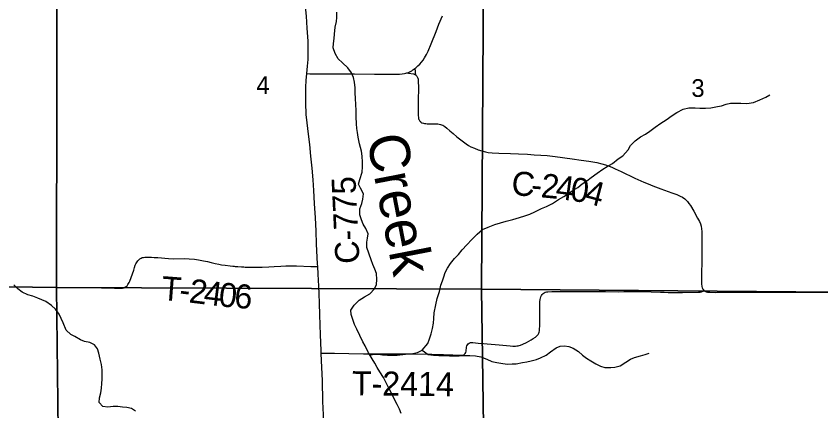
# Model space of a CAD drawing. Extents: x 1874609 to 2204689, y 815661 to 1281160.
# Drawn here: x 2023837 to 2033877, y 986389 to 991319 of the extents above; entities that cross this region are included whole.
import ezdxf

# ---------------------------------------------------------------- set-up
doc = ezdxf.new("R2010")
doc.units = 0
for name, color, linetype in [('GM_X_County_Road', 7, 'Continuous'), ('GM_X_County_Road_Text', 7, 'Continuous'), ('GM_X_Minor_River', 7, 'Continuous'), ('GM_X_Minor_River_Text', 7, 'Continuous'), ('GM_X_Section', 7, 'Continuous'), ('GM_X_Section_Text', 7, 'Continuous'), ('GM_X_Township_Road', 7, 'Continuous'), ('GM_X_Township_Road_Text', 7, 'Continuous')]:
    doc.layers.add(name, color=color, linetype=linetype)

msp = doc.modelspace()

# ---------------------------------------------------------------- linework, layer by layer
at = {"layer": 'GM_X_County_Road'}
for points in [[(2027465, 990602), (2027473, 990694), (2027480, 990776), (2027481, 990841), (2027482, 990940), (2027479, 991006), (2027469, 991169), (2027458, 991317), (2027449, 991398), (2027439, 991463), (2027425, 991528), (2027407, 991608), (2027369, 991750), (2027342, 991845), (2027290, 992035), (2027252, 992177), (2027215, 992320), (2027154, 992575), (2027096, 992831), (2027074, 992944), (2027062, 993008), (2027054, 993073), (2027048, 993138), (2027047, 993160)], [(2028812, 990664), (2028825, 990674), (2028850, 990696), (2028873, 990719), (2028894, 990743), (2028914, 990769), (2028932, 990796), (2028956, 990838), (2028977, 990882), (2029014, 990973), (2029075, 991126), (2029112, 991217), (2029157, 991323)], [(2028712, 990610), (2028719, 990612), (2028731, 990616), (2028744, 990622), (2028757, 990629), (2028772, 990637), (2028787, 990647), (2028799, 990655), (2028807, 990660), (2028812, 990664)], [(2028812, 990664), (2028812, 990656), (2028814, 990635), (2028815, 990621), (2028816, 990610), (2028818, 990591), (2028818, 990587)], [(2027600, 988191), (2027598, 988226), (2027586, 988472), (2027579, 988636), (2027571, 988800), (2027561, 988980), (2027551, 989143), (2027548, 989208), (2027543, 989274), (2027529, 989421), (2027514, 989568), (2027499, 989714), (2027488, 989812), (2027457, 990089), (2027454, 990139), (2027450, 990187), (2027449, 990269), (2027449, 990318), (2027452, 990432), (2027456, 990514), (2027465, 990602)], [(2027465, 990602), (2027503, 990600), (2027568, 990598), (2027634, 990597), (2027749, 990596), (2028060, 990596), (2028307, 990595), (2028536, 990593), (2028618, 990595), (2028651, 990598), (2028683, 990602), (2028699, 990606), (2028712, 990610)], [(2028712, 990610), (2028733, 990607), (2028794, 990596), (2028801, 990594), (2028807, 990592), (2028812, 990590), (2028815, 990588), (2028818, 990587)], [(2028818, 990587), (2028821, 990585), (2028823, 990583), (2028827, 990580), (2028832, 990574), (2028837, 990567), (2028840, 990561), (2028844, 990553), (2028848, 990543), (2028851, 990531), (2028853, 990516), (2028854, 990499), (2028855, 990434), (2028853, 990254), (2028854, 990072), (2028855, 990056), (2028858, 990039), (2028861, 990029), (2028864, 990023), (2028869, 990014), (2028873, 990008), (2028880, 990001), (2028886, 989996), (2028900, 989988), (2028917, 989982), (2028933, 989978), (2028950, 989976), (2028964, 989975), (2028983, 989975), (2029082, 989973), (2029099, 989972), (2029113, 989970), (2029129, 989967), (2029144, 989962), (2029159, 989955), (2029173, 989948), (2029186, 989939), (2029212, 989919), (2029249, 989887), (2029287, 989855), (2029336, 989813), (2029400, 989761), (2029453, 989722), (2029481, 989704), (2029510, 989688), (2029555, 989668), (2029600, 989650), (2029647, 989635), (2029694, 989622), (2029727, 989616), (2029776, 989611), (2029858, 989608), (2030005, 989604), (2030104, 989601), (2030218, 989593), (2030300, 989587), (2030382, 989583), (2030463, 989577), (2030561, 989566), (2030772, 989537), (2030886, 989522), (2030983, 989508), (2031080, 989490), (2031143, 989476), (2031190, 989463), (2031237, 989446), (2031267, 989434), (2031311, 989413), (2031385, 989379), (2031554, 989297), (2031669, 989247), (2031721, 989226), (2031780, 989201), (2031879, 989161), (2032016, 989114), (2032078, 989092), (2032122, 989072), (2032150, 989056), (2032177, 989038), (2032200, 989016), (2032211, 989004), (2032231, 988979), (2032249, 988952), (2032290, 988882), (2032339, 988797), (2032361, 988754), (2032374, 988725), (2032383, 988694), (2032389, 988663), (2032392, 988631), (2032393, 988582), (2032393, 988500), (2032392, 988368), (2032391, 988237), (2032389, 988122), (2032388, 988040), (2032389, 987975), (2032393, 987942), (2032396, 987925), (2032403, 987909), (2032419, 987889)], [(2027644, 987111), (2027643, 987145), (2027635, 987341), (2027625, 987587), (2027621, 987735), (2027617, 987850), (2027613, 987948), (2027606, 988095), (2027600, 988191)], [(2032419, 987889), (2032444, 987875), (2032460, 987873), (2032492, 987870), (2032558, 987869), (2032672, 987870), (2032738, 987871), (2032804, 987871), (2032885, 987871), (2032999, 987871), (2033081, 987870), (2033179, 987870), (2033393, 987870), (2033458, 987870), (2033556, 987871), (2033687, 987871), (2033785, 987871), (2033999, 987869)], [(2027701, 985206), (2027703, 985275), (2027700, 985423), (2027691, 985685), (2027674, 986259), (2027665, 986505), (2027657, 986768), (2027646, 987013), (2027644, 987111)]]:
    msp.add_lwpolyline(points, dxfattribs=at)
at = {"layer": 'GM_X_Minor_River'}
for points in [[(2028331, 987968), (2028337, 988030), (2028331, 988104), (2028311, 988158), (2028287, 988219), (2028265, 988277), (2028213, 988429), (2028213, 988495), (2028219, 988547), (2028227, 988600), (2028201, 988668), (2028167, 988722), (2028145, 988776), (2028126, 988836), (2028124, 988912), (2028148, 988981), (2028162, 989035), (2028170, 989101), (2028132, 989169), (2028108, 989219), (2028126, 989277), (2028152, 989372), (2028156, 989436), (2028156, 989496), (2028152, 989568), (2028144, 989632), (2028121, 989724), (2028103, 989807), (2028095, 989867), (2028089, 989917), (2028085, 989975), (2028079, 990063), (2028081, 990132), (2028075, 990222), (2028069, 990282), (2028067, 990368), (2028065, 990422), (2028057, 990492), (2028047, 990551), (2028021, 990611), (2027973, 990671), (2027909, 990735), (2027855, 990785), (2027817, 990850), (2027793, 990922), (2027797, 990978), (2027805, 991038), (2027809, 991092), (2027818, 991180), (2027832, 991251), (2027836, 991303), (2027836, 991367)], [(2028251, 987086), (2028300, 987098), (2028354, 987096), (2028408, 987088), (2028470, 987084), (2028522, 987084), (2028589, 987086), (2028663, 987092), (2028729, 987100), (2028787, 987106), (2028845, 987118), (2028903, 987148), (2028971, 987230), (2028994, 987288), (2029014, 987350), (2029030, 987420), (2029042, 987486), (2029046, 987543), (2029054, 987613), (2029072, 987713), (2029088, 987793), (2029119, 987879), (2029137, 987958), (2029155, 988012), (2029171, 988062), (2029191, 988116), (2029217, 988170), (2029257, 988228), (2029305, 988292), (2029354, 988342), (2029402, 988401), (2029458, 988463), (2029522, 988531), (2029588, 988597), (2029657, 988653), (2029727, 988683), (2029809, 988717), (2029881, 988737), (2029949, 988757), (2030034, 988779), (2030116, 988805), (2030184, 988825), (2030246, 988847), (2030306, 988873), (2030390, 988917), (2030455, 988943), (2030529, 988981), (2030605, 989030), (2030669, 989066), (2030727, 989104), (2030788, 989146), (2030844, 989178), (2030900, 989224), (2030958, 989264), (2031010, 989302), (2031086, 989358), (2031155, 989406), (2031209, 989442), (2031275, 989480), (2031349, 989537), (2031405, 989575), (2031472, 989649), (2031502, 989705), (2031558, 989761), (2031626, 989813), (2031690, 989845), (2031742, 989883), (2031809, 989931), (2031879, 989981), (2031947, 990025), (2032019, 990076), (2032081, 990116), (2032158, 990156), (2032230, 990174), (2032306, 990174), (2032366, 990168), (2032438, 990168), (2032502, 990174), (2032585, 990188), (2032637, 990200), (2032695, 990220), (2032749, 990232), (2032823, 990232), (2032877, 990230), (2032953, 990228), (2033036, 990240), (2033114, 990274), (2033190, 990306), (2033240, 990334)], [(2025327, 986387), (2025277, 986419), (2025219, 986431), (2025162, 986438), (2025104, 986446), (2025046, 986444), (2024980, 986436), (2024920, 986444), (2024872, 986496), (2024878, 986552), (2024892, 986614), (2024904, 986672), (2024908, 986730), (2024910, 986787), (2024910, 986901), (2024901, 986967), (2024887, 987037), (2024869, 987109), (2024851, 987164), (2024813, 987214), (2024757, 987242), (2024692, 987258), (2024642, 987278), (2024570, 987318), (2024520, 987344), (2024460, 987398), (2024422, 987491), (2024398, 987543), (2024374, 987597), (2024330, 987661), (2024278, 987707), (2024208, 987755), (2024158, 987775), (2024108, 987797), (2024046, 987820), (2023982, 987838), (2023913, 987872), (2023859, 987914), (2023807, 987964)], [(2028642, 986358), (2028618, 986410), (2028590, 986468), (2028554, 986542), (2028518, 986610), (2028484, 986683), (2028454, 986741), (2028420, 986807), (2028376, 986877), (2028340, 986933), (2028310, 986985), (2028278, 987038), (2028234, 987116), (2028190, 987200), (2028164, 987252), (2028124, 987330), (2028086, 987409), (2028060, 987467), (2028036, 987529), (2028016, 987595), (2028014, 987647), (2028054, 987709), (2028116, 987770), (2028184, 987814), (2028249, 987852), (2028309, 987912), (2028331, 987968)], [(2028903, 987148), (2028977, 987095), (2029045, 987087), (2029112, 987083), (2029186, 987083), (2029244, 987079), (2029306, 987077), (2029364, 987079), (2029434, 987081), (2029498, 987081), (2029567, 987077), (2029635, 987063), (2029711, 987035), (2029773, 987007), (2029835, 986993), (2029907, 986981), (2029967, 986975), (2030023, 986977), (2030076, 986979), (2030152, 986993), (2030208, 987003), (2030264, 987015), (2030328, 987033), (2030380, 987051), (2030448, 987085), (2030505, 987129), (2030573, 987177), (2030625, 987199), (2030679, 987203), (2030733, 987193), (2030787, 987171), (2030853, 987131), (2030903, 987086), (2030953, 987048), (2031006, 987014), (2031068, 986976), (2031128, 986948), (2031182, 986932), (2031254, 986930), (2031304, 986934), (2031374, 986954), (2031442, 986998), (2031501, 987034), (2031551, 987056), (2031627, 987078), (2031683, 987092), (2031735, 987110)]]:
    msp.add_lwpolyline(points, dxfattribs=at)
at = {"layer": 'GM_X_Section'}
for points in [[(2019028, 993166), (2024347, 993135), (2024339, 987929), (2018951, 988004)], [(2024347, 993135), (2024403, 993136), (2029677, 993105), (2029642, 987908), (2024339, 987929)], [(2029677, 993105), (2035022, 993074), (2035033, 987863), (2029642, 987908)], [(2024339, 987929), (2024405, 982561), (2019042, 982641), (2018951, 988004)], [(2029642, 987908), (2029723, 982510), (2024405, 982561), (2024339, 987929)], [(2035033, 987863), (2035040, 982545), (2029723, 982510), (2029642, 987908)]]:
    msp.add_lwpolyline(points, close=True, dxfattribs=at)
at = {"layer": 'GM_X_Township_Road'}
for points in [[(2024901, 987928), (2024983, 987926), (2025065, 987922), (2025115, 987920), (2025147, 987920), (2025164, 987922), (2025180, 987927), (2025195, 987933), (2025208, 987942), (2025221, 987953), (2025231, 987966), (2025240, 987979), (2025248, 987994), (2025255, 988009), (2025271, 988055), (2025304, 988148), (2025315, 988179), (2025324, 988209), (2025331, 988224), (2025339, 988238), (2025347, 988252), (2025357, 988265), (2025368, 988277), (2025377, 988284)], [(2025377, 988284), (2025381, 988288), (2025395, 988296), (2025410, 988303), (2025426, 988306), (2025442, 988308), (2025475, 988310), (2025524, 988308), (2025557, 988306), (2025606, 988303), (2025736, 988293), (2025801, 988290), (2025932, 988292), (2025997, 988289), (2026062, 988284), (2026111, 988277), (2026175, 988264), (2026223, 988253), (2026271, 988242), (2026318, 988231), (2026366, 988221), (2026398, 988215), (2026446, 988207), (2026509, 988200), (2026540, 988196), (2026555, 988195), (2026571, 988194), (2026586, 988192), (2026602, 988191), (2026648, 988188), (2026679, 988187), (2026695, 988186), (2026711, 988186), (2026760, 988184), (2026793, 988184), (2026842, 988185), (2026908, 988186), (2026990, 988189), (2027056, 988193), (2027138, 988198), (2027203, 988200), (2027285, 988200), (2027334, 988199), (2027515, 988192), (2027564, 988192), (2027600, 988191)], [(2029371, 987085), (2029381, 987085), (2029397, 987084), (2029414, 987087), (2029428, 987094), (2029439, 987106), (2029447, 987120), (2029451, 987135), (2029457, 987184), (2029461, 987200), (2029467, 987215), (2029477, 987228), (2029489, 987237), (2029504, 987243), (2029520, 987245), (2029536, 987245), (2029602, 987237), (2029666, 987231), (2029715, 987226), (2029763, 987221), (2029861, 987213), (2029907, 987210), (2029954, 987205), (2030002, 987201), (2030034, 987199), (2030066, 987199), (2030082, 987201), (2030098, 987203), (2030114, 987206), (2030130, 987211), (2030160, 987222), (2030204, 987244), (2030261, 987275), (2030288, 987292), (2030315, 987310), (2030328, 987321), (2030339, 987332), (2030349, 987345), (2030357, 987359), (2030363, 987374), (2030366, 987390), (2030368, 987407), (2030369, 987456), (2030369, 987521), (2030369, 987619), (2030369, 987701), (2030370, 987750), (2030374, 987782), (2030378, 987798), (2030382, 987814), (2030389, 987829), (2030399, 987842), (2030410, 987854), (2030423, 987864), (2030437, 987871), (2030453, 987875), (2030469, 987877), (2030518, 987879), (2030600, 987879), (2030665, 987879), (2030861, 987881), (2031025, 987881), (2031189, 987880), (2031352, 987878), (2031418, 987879), (2031532, 987882), (2031581, 987882), (2031631, 987882), (2031696, 987880), (2031761, 987878), (2031874, 987873), (2031923, 987871), (2031972, 987869), (2032053, 987868), (2032152, 987869), (2032348, 987872), (2032362, 987872), (2032371, 987873), (2032385, 987876), (2032394, 987879), (2032419, 987889)], [(2027644, 987111), (2027695, 987110), (2027743, 987110), (2027809, 987109), (2027989, 987106), (2028169, 987103), (2028317, 987102), (2028546, 987102), (2028792, 987102), (2029021, 987099), (2029168, 987095), (2029283, 987090), (2029371, 987085)]]:
    msp.add_lwpolyline(points, dxfattribs=at)

# ---------------------------------------------------------------- texts
at = {"layer": 'GM_X_County_Road_Text'}
for s, rotation, p in [('C', 355.636, (2030009, 989086)), ('2', 354.5431, (2030376, 989057)), ('C-775', 92.7564, (2028122, 988233)), ('4', 352.6368, (2030557, 989040)), ('0', 351.839, (2030739, 989016)), ('4', 345.2292, (2030913, 988992)), ('-', 355.3504, (2030254, 989067))]:
    msp.add_text(s, height=300, rotation=rotation, dxfattribs=at).set_placement(p)
at = {"layer": 'GM_X_Minor_River_Text'}
msp.add_text('Creek', height=500.1, rotation=280.9515, dxfattribs=at).set_placement((2028208, 989804))
at = {"layer": 'GM_X_Section_Text'}
for s, p in [('4', (2026834, 990347)), ('3', (2032261, 990310))]:
    msp.add_text(s, height=221, rotation=0, dxfattribs=at).set_placement(p)
at = {"layer": 'GM_X_Township_Road_Text'}
for s, rotation, p in [('T', 355.6158, (2025641, 987774)), ('2', 353.1196, (2025984, 987744)), ('4', 353.1035, (2026167, 987721)), ('0', 353.6477, (2026354, 987699)), ('6', 356.12, (2026552, 987677)), ('-', 353.4676, (2025862, 987758)), ('T-2414', 359.3122, (2028025, 986586))]:
    msp.add_text(s, height=300, rotation=rotation, dxfattribs=at).set_placement(p)

doc.saveas('drawing.dxf')
